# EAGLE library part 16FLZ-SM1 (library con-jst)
CONNECTOR
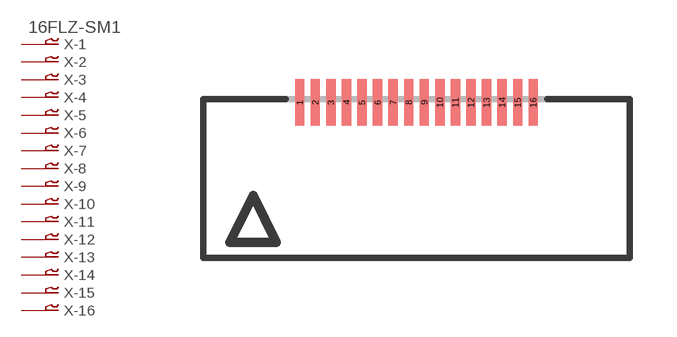
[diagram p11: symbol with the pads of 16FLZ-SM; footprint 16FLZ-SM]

Designator prefix X; gates -1=P-VN -2=P-N -3=P-N -4=P-N -5=P-N -6=P-N -7=P-N -8=P-N -9=P-N -10=P-N -11=P-N -12=P-N -13=P-N -14=P-N -15=P-N -16=P-N

## 16FLZ-SM1 (OC_FARNELL: unknown; OC_NEWARK: unknown)  [16FLZ-SM]
1  -1:1  pas
2  -2:1  pas
3  -3:1  pas
4  -4:1  pas
5  -5:1  pas
6  -6:1  pas
7  -7:1  pas
8  -8:1  pas
9  -9:1  pas
10  -10:1  pas
11  -11:1  pas
12  -12:1  pas
13  -13:1  pas
14  -14:1  pas
15  -15:1  pas
16  -16:1  pas

## Footprint 16FLZ-SM (pad centres in mm)
CONNECTOR
smd 0.3 x 1.5: 1 -3.75,2.5; 2 -3.25,2.5; 3 -2.75,2.5; 4 -2.25,2.5; 5 -1.75,2.5; 6 -1.25,2.5; 7 -0.75,2.5; 8 -0.25,2.5; 9 0.25,2.5; 10 0.75,2.5; 11 1.25,2.5; 12 1.75,2.5; 13 2.25,2.5; 14 2.75,2.5; 15 3.25,2.5; 16 3.75,2.5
